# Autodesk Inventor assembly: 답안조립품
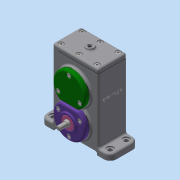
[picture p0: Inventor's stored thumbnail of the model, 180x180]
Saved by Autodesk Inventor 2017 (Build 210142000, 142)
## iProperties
Part Number: 답안조립품
Material: 일반
Document SubType Name: Assembly
Designer: 222
Author: 222
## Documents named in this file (24)
- C:\Users\222\Desktop\600506V1018\답안조립품.iam
- C:\Users\222\Desktop\600506V1018\본체.ipt
- C:\Users\222\Desktop\600506V1018\Ű 4 x 4 x 12.ipt
- C:\Users\222\Desktop\600506V1018\Ű 5 x 5 x 12.ipt
- C:\Users\222\Desktop\600506V1018\개스킷 A.ipt
- C:\Users\222\Desktop\600506V1018\개스킷 B.ipt
- C:\Users\222\Desktop\600506V1018\개스킷 C.ipt
- C:\Users\222\Desktop\600506V1018\베어링 6001.ipt
- 베어링 6001.ipt
- C:\Users\222\Desktop\600506V1018\베어링 6002.ipt
- 베어링 6002.ipt
- C:\Users\222\Desktop\600506V1018\볼트 M4.ipt
- C:\Users\222\Desktop\600506V1018\스퍼기어 A.ipt
- C:\Users\222\Desktop\600506V1018\스퍼기어 B.ipt
- C:\Users\222\Desktop\600506V1018\오일 실 10 20 7.ipt
- C:\Users\222\Desktop\600506V1018\오일 실 12 22 7.ipt
- C:\Users\222\Desktop\600506V1018\축 A.ipt
- C:\Users\222\Desktop\600506V1018\축 B.ipt
- C:\Users\222\Desktop\600506V1018\칼라.ipt
- C:\Users\222\Desktop\600506V1018\커버 A.ipt
- C:\Users\222\Desktop\600506V1018\커버 B.ipt
- C:\Users\222\Desktop\600506V1018\커버 C.ipt
- C:\Users\222\Desktop\600506V1018\커버 D.ipt
- C:\Users\222\Desktop\600506V1018\커버 E.ipt
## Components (7 placed, 5 different names)
1. Ű 4 x 4 x 12:1
2. Ű 5 x 5 x 12:1
3. 개스킷 A:1
4. 개스킷 B:1
5. 개스킷 C:1
6. 개스킷 B:2
7. 개스킷 B:3
